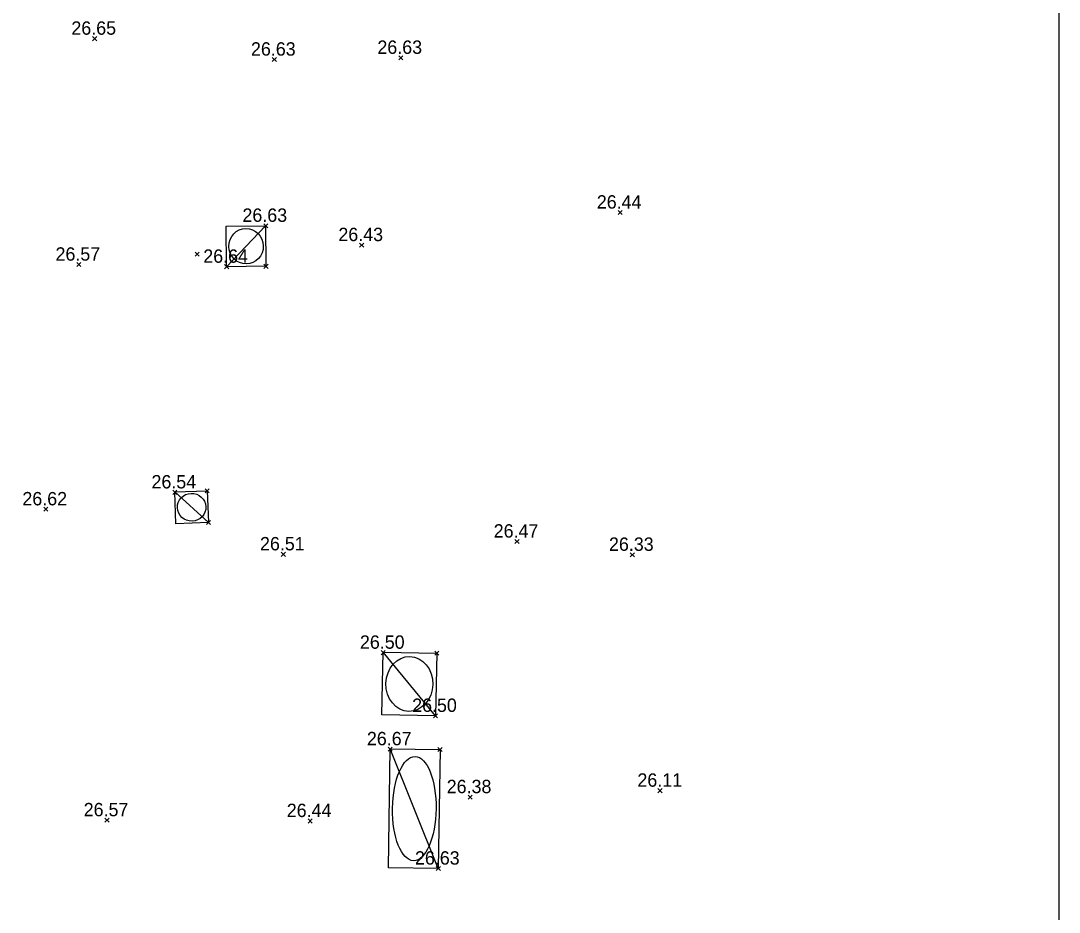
# Model space of a CAD drawing. Extents: x 37864 to 38032, y 453991 to 454052.
# Drawn here: x 37923.89 to 37946.06, y 454009.85 to 454028.87 of the extents above; entities that cross this region are included whole.
import ezdxf

# ---------------------------------------------------------------- set-up
doc = ezdxf.new("R2010")
doc.units = 0
for name, color, linetype in [('DH_CALCUL SURFACE-TEXTE', 7, 'Continuous'), ('DH_TEXTE', 7, 'Continuous'), ('GO_POTEAU', 7, 'Continuous')]:
    doc.layers.add(name, color=color, linetype=linetype)

# ---------------------------------------------------------------- blocks, each defined once
blk = doc.blocks.new('A-REGARD')
for p, q in [((0, 1), (1, 1)), ((0, 0), (1, 1)), ((0, 0), (0, 1)), ((1, 1), (1, 0)), ((0.5, 0), (0, 0)), ((1, 0), (0.5, 0))]:
    blk.add_line(p, q)
blk.add_circle((0.5, 0.5), 0.4375)
blk = doc.blocks.new('POINT_DISPLAY')
for p, q in [((-0.04375, -0.04375), (0.04375, 0.04375)), ((-0.04375, 0.04375), (0.04375, -0.04375))]:
    blk.add_line(p, q)
blk = doc.blocks.new('POINTCOT')
blk.add_blockref('POINT_DISPLAY', (0, 0))

msp = doc.modelspace()

# ---------------------------------------------------------------- linework, layer by layer
at = {"layer": 'DEFPOINTS'}
msp.add_lwpolyline([(37864.064, 453990.816), (37946.064, 453990.816), (37946.064, 454048.216), (37864.064, 454048.216)], close=True, dxfattribs=at)

# ---------------------------------------------------------------- block references
at = {"layer": 'DH_CALCUL SURFACE-TEXTE', "rotation": 2.2526485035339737e-05}
for p in [(37925.473, 454028.493), (37929.307, 454028.047), (37932.006, 454028.086), (37936.69, 454024.782), (37929.125, 454024.499), (37931.173, 454024.087), (37927.661, 454023.892), (37925.134, 454023.67), (37928.289, 454023.625), (37929.13, 454023.634), (37927.183, 454018.809), (37927.876, 454018.843), (37924.427, 454018.448), (37927.902, 454018.165), (37934.489, 454017.759), (37929.5, 454017.486), (37936.95, 454017.476), (37931.633, 454015.386), (37932.775, 454015.377), (37932.748, 454014.038), (37931.782, 454013.326), (37932.845, 454013.321), (37937.542, 454012.441), (37933.486, 454012.304), (37925.736, 454011.81), (37930.071, 454011.793), (37932.808, 454010.778)]:
    msp.add_blockref('POINTCOT', p, dxfattribs=at)
at = {"layer": 'DH_TEXTE'}
for p, xscale, yscale, rotation in [((37928.289, 454023.625), 0.8405976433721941, 0.8649244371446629, 0.5874476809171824), ((37927.902, 454018.165), 0.6783939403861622, 0.694276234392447, 92.20430036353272), ((37932.748, 454014.038), 1.3387789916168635, 1.1424645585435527, 88.84200297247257), ((37932.808, 454010.778), 2.543198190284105, 1.0632295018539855, 89.15963548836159)]:
    msp.add_blockref('A-REGARD', p, dxfattribs=dict(at, xscale=xscale, yscale=yscale, rotation=rotation))

# ---------------------------------------------------------------- texts
at = {"layer": 'GO_POTEAU'}
for s, p in [('26.65', (37924.975, 454028.577)), ('26.63', (37928.809, 454028.131)), ('26.63', (37931.508, 454028.169)), ('26.44', (37936.192, 454024.866)), ('26.63', (37928.627, 454024.583)), ('26.43', (37930.675, 454024.171)), ('26.57', (37924.636, 454023.754)), ('26.64', (37927.791, 454023.709)), ('26.54', (37926.685, 454018.892)), ('26.62', (37923.929, 454018.531)), ('26.47', (37933.991, 454017.843)), ('26.51', (37929.002, 454017.57)), ('26.33', (37936.452, 454017.56)), ('26.50', (37931.135, 454015.47)), ('26.50', (37932.25, 454014.122)), ('26.67', (37931.284, 454013.41)), ('26.38', (37932.988, 454012.387)), ('26.11', (37937.059, 454012.525)), ('26.57', (37925.238, 454011.894)), ('26.44', (37929.573, 454011.877)), ('26.63', (37932.31, 454010.862))]:
    msp.add_text(s, height=0.285, rotation=0, dxfattribs=at).set_placement(p)

doc.saveas('drawing.dxf')
